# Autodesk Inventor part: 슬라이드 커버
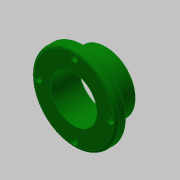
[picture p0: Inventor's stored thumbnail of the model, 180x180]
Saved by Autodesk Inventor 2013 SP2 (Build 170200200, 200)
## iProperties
Created: 2015-10
Part Number: 슬라이드 커버
Document SubType Name: Modeling
Designer: mdu
Density: 2.71 g/cm^3
Material: 알루미늄 6061
Mass: 206.361 g
Surface Area: 229.996 cm^2
Volume: 76.148 cm^3
Author: mdu
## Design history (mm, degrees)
sketch "스케치1"
  geometry: C1 r 46 at (0, -39.25) reference; C2 r 32.5 at (0, -39.25) reference; 1 further point
  node "참조1"
  node "참조2"
extrude "돌출1" new body sketch "스케치1" distance "d0" = 10; taper "d1" = 0 deg
extrude "돌출2" join sketch "스케치1" distance "d2" = 25; taper "d3" = 0 deg
hole "구멍1" diameter "d6" = 50; stored, may be unused: countersink angle "d10" = 90 deg, drill point angle "d12" = 118 deg; dims "d4" = 10, "d5" = 10, "d7" = 6, "d8" = 4, "d9" = 2, "d11" = 8
sketch "스케치2"
  geometry: C1 r 46 at (0, 0) reference; C2 r 1.621 at (0, 39) reference; C3 r 1.621 at (39, 0) reference; C4 r 1.621 at (0, -39) reference; C5 r 1.621 at (-39, 0) reference; C6 r 33.5 at (0, 0) reference; 1 further point
hole "구멍2" sketch "스케치2" at (0, 39) diameter "d13" = 4.5; stored, may be unused: countersink angle "d17" = 90 deg, drill point angle "d19" = 118 deg; dims "d14" = 6, "d15" = 8, "d16" = 4.4, "d18" = 8
fillet "모깎기1" dims "d23" = 3
chamfer "모따기1" distance "d24" = 1; stored, may be unused: second distance "d25" = 2, angle "d26" = 45 deg
sketch "스케치3"
  geometry: C1 r 25 at (0, 0); C2 r 30 at (0, 0); C3 r 26 at (0, 0) reference; 1 further point
  constraints: 2 centre point, 2 coincident
  dimensions: "d27" = 60 diameter of C2
extrude "돌출3" cut sketch "스케치3" distance "d28" = 3; taper "d29" = 0 deg
chamfer "모따기2" distance "d30" = 1; stored, may be unused: second distance "d31" = 2, angle "d32" = 45 deg
node "솔리드1"
pattern_circular "원형 패턴1" dims angle "d21" = 360 deg
node "참조3"
